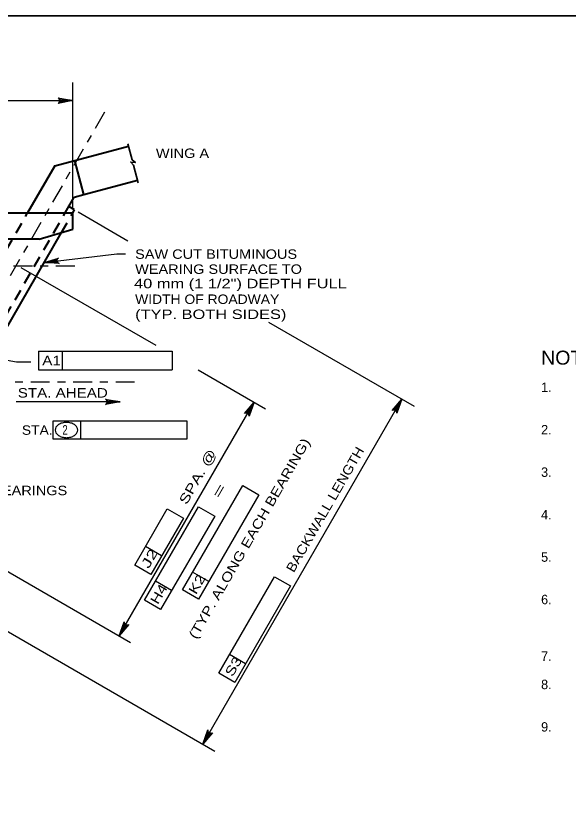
# Model space of a CAD drawing. Extents: x -11 to 79, y -154 to 0.
# Drawn here: x 16.53 to 23.56, y -120.79 to -110.75 of the extents above; entities that cross this region are included whole.
import ezdxf
from ezdxf.enums import TextEntityAlignment as Align

# ---------------------------------------------------------------- set-up
doc = ezdxf.new("R2010")
doc.units = 0
doc.header["$LTSCALE"] = 0.048
doc.linetypes.add('DOT_DASHED', pattern=[7.7, 5, -1.2, 0.3, -1.2])
doc.linetypes.add('MEDIUM_DASHED', pattern=[4.5, 3, -1.5])
for name, color, linetype, lineweight in [('1', 7, 'Continuous', 25), ('2', 7, 'Continuous', 35), ('3', 7, 'Continuous', 25), ('4', 7, 'Continuous', 25)]:
    doc.layers.add(name, color=color, linetype=linetype, lineweight=lineweight)

msp = doc.modelspace()

# ---------------------------------------------------------------- hatches: boundary and pattern name
at = {"layer": '4'}
for points in [[(21.36575, -115.71767), (21.40042, -115.73767), (21.44308, -115.62375)], [(19.48925, -115.75067), (19.522, -115.76958), (19.56233, -115.66192)], [(17.8855, -118.52842), (17.91825, -118.54733), (17.84517, -118.63608)]]:
    msp.add_hatch(color=256, dxfattribs=at).paths.add_polyline_path(points)

# ---------------------------------------------------------------- linework, layer by layer
at = {"layer": '1', "lineweight": 35}
msp.add_lwpolyline([(1.75, -131.25), (33.25, -131.25), (33.25, -110.75), (1.75, -110.75)], close=True, dxfattribs=at)
at = {"layer": '2', "lineweight": 40}
for p, q in [((17.02708, -112.66017), (17.96425, -112.409)), ((17.39675, -113.02383), (17.28108, -112.59208)), ((17.02708, -112.66017), (16.68192, -113.258)), ((17.39675, -113.02383), (18.07992, -112.84075)), ((17.27575, -113.05625), (17.39675, -113.02383)), ((17.15925, -113.258), (17.27575, -113.05625)), ((17.2795, -113.21992), (17.20583, -113.17733)), ((17.25742, -113.25808), (17.2795, -113.21992)), ((9.11433, -113.25808), (17.25742, -113.25808)), ((9.33183, -113.258), (17.15925, -113.258)), ((17.25742, -113.46475), (17.25742, -113.25808)), ((14.91208, -117.32042), (17.11392, -113.50675)), ((16.82825, -113.59025), (17.25742, -113.46475)), ((16.82825, -113.59025), (9.61733, -113.59025))]:
    msp.add_line(p, q, dxfattribs=at)
at = {"layer": '2', "linetype": 'MEDIUM_DASHED', "lineweight": 40}
for p, q in [((14.21717, -117.52708), (16.68192, -113.258)), ((17.01567, -113.50667), (17.15925, -113.258)), ((17.11392, -113.50675), (17.25742, -113.25808)), ((14.81383, -117.32042), (17.01567, -113.50667))]:
    msp.add_line(p, q, dxfattribs=at)
at = {"layer": '3', "lineweight": 35}
for p, q in [((18.011, -112.5835), (17.956, -112.3785)), ((18.08883, -112.87417), (18.02883, -112.65017))]:
    msp.add_line(p, q, dxfattribs=at)
msp.add_lwpolyline([(18.011, -112.5835), (18.053, -112.61483), (17.99325, -112.61125), (18.02883, -112.65017)], dxfattribs=at)
at = {"layer": '4'}
for p, q in [((17.25742, -112.23542), (17.25742, -111.59975)), ((9.11433, -111.82925), (17.25742, -111.82925)), ((17.25742, -113.19375), (17.25742, -112.23542)), ((17.32317, -113.24508), (17.95842, -113.61192)), ((16.89358, -113.88833), (17.81508, -113.77775)), ((17.81508, -113.77775), (17.9285, -113.77775)), ((16.59658, -113.94958), (18.31108, -114.9395)), ((19.747, -114.64458), (21.599, -115.71383)), ((16.81958, -115.01583), (18.52033, -115.01583)), ((16.81958, -115.01583), (16.81958, -115.252)), ((17.122, -115.01583), (17.122, -115.252)), ((18.52033, -115.01583), (18.52033, -115.252)), ((16.29683, -115.10933), (16.54258, -115.15067)), ((16.54258, -115.15067), (16.7215, -115.15067)), ((16.81958, -115.252), (18.52033, -115.252)), ((18.84983, -115.25058), (19.70958, -115.74692)), ((18.90975, -120.01167), (21.44308, -115.62375)), ((17.85825, -115.65892), (16.5365, -115.65892)), ((17.84517, -118.636), (19.56233, -115.66192)), ((17.84517, -118.63608), (19.56233, -115.66192)), ((17.35692, -116.136), (17.35692, -115.89983)), ((18.65017, -118.05083), (19.41967, -116.7235)), ((19.41967, -116.7235), (19.62425, -116.84158)), ((19.62425, -116.84158), (18.85475, -118.169)), ((14.87942, -116.92375), (17.9925, -118.72108)), ((18.16883, -118.1805), (18.85783, -116.99625)), ((18.85783, -116.99625), (19.06242, -117.11433)), ((19.06242, -117.11433), (18.37342, -118.29858)), ((18.38675, -117.61708), (18.18225, -117.499)), ((14.80025, -117.63908), (19.06558, -120.10167)), ((18.249, -117.85575), (18.04442, -117.73767)), ((18.98533, -117.94283), (18.78075, -117.82475)), ((18.512, -118.06042), (18.30783, -117.94158)), ((19.11258, -119.11192), (19.82192, -117.88342)), ((19.82192, -117.88342), (20.02642, -118.0015)), ((18.85475, -118.169), (18.65017, -118.05083)), ((18.37342, -118.29858), (18.16883, -118.1805)), ((19.455, -118.99133), (19.25042, -118.87325))]:
    msp.add_line(p, q, dxfattribs=at)
at = {"layer": '4', "linetype": 'DOT_DASHED'}
for p, q in [((17.66008, -111.97717), (13.89925, -118.49117)), ((17.28283, -113.93625), (3.36083, -113.93625)), ((18.04217, -115.40917), (6.3505, -115.40917))]:
    msp.add_line(p, q, dxfattribs=at)
at = {"layer": '4'}
for points in [[(17.25742, -111.82925), (17.071, -111.86417), (17.08533, -111.85425), (17.09275, -111.84175), (17.09492, -111.82925), (17.09275, -111.81675), (17.08533, -111.80425), (17.071, -111.79433), (17.25742, -111.82925), (17.08533, -111.80425), (17.09275, -111.81675), (17.25742, -111.82925), (17.09492, -111.82925), (17.09275, -111.84175), (17.25742, -111.82925), (17.08533, -111.85425)], [(16.89358, -113.88833), (17.0745, -113.83142), (17.06142, -113.843), (17.05558, -113.85633), (17.05492, -113.869), (17.05858, -113.88117), (17.06742, -113.89267), (17.08283, -113.90083), (16.89358, -113.88833), (17.06742, -113.89267), (17.05858, -113.88117), (16.89358, -113.88833), (17.05492, -113.869), (17.05558, -113.85633), (16.89358, -113.88833), (17.06142, -113.843)], [(17.85825, -115.65892), (17.67183, -115.69383), (17.68617, -115.68392), (17.69358, -115.67142), (17.69575, -115.65892), (17.69358, -115.64642), (17.68617, -115.63392), (17.67183, -115.624), (17.85825, -115.65892), (17.68617, -115.63392), (17.69358, -115.64642), (17.85825, -115.65892), (17.69575, -115.65892), (17.69358, -115.67142), (17.85825, -115.65892), (17.68617, -115.68392)], [(21.44308, -115.62375), (21.38017, -115.80267), (21.37875, -115.78525), (21.37158, -115.77258), (21.36183, -115.7645), (21.34992, -115.76008), (21.33542, -115.76025), (21.31958, -115.76775), (21.44308, -115.62375), (21.33542, -115.76025), (21.34992, -115.76008), (21.44308, -115.62375), (21.36183, -115.7645), (21.37158, -115.77258), (21.44308, -115.62375), (21.37875, -115.78525)], [(19.56233, -115.66192), (19.49942, -115.84083), (19.49792, -115.82342), (19.49083, -115.81075), (19.48108, -115.80267), (19.46917, -115.79825), (19.45467, -115.79842), (19.43883, -115.80592), (19.56233, -115.66192), (19.45467, -115.79842), (19.46917, -115.79825), (19.56233, -115.66192), (19.48108, -115.80267), (19.49083, -115.81075), (19.56233, -115.66192), (19.49792, -115.82342)], [(18.04442, -117.73767), (18.45892, -117.01975), (18.6635, -117.13792), (18.249, -117.85575)], [(20.02642, -118.0015), (19.31717, -119.23), (19.11258, -119.11192)], [(17.84517, -118.636), (17.90808, -118.45708), (17.90958, -118.4745), (17.91667, -118.48717), (17.92642, -118.49525), (17.93833, -118.49967), (17.95283, -118.4995), (17.96867, -118.492), (17.84517, -118.636), (17.95283, -118.4995), (17.93833, -118.49967), (17.84517, -118.636), (17.92642, -118.49525), (17.91667, -118.48717), (17.84517, -118.636), (17.90958, -118.4745)], [(18.90975, -120.01167), (18.97267, -119.83275), (18.97408, -119.85017), (18.98125, -119.86283), (18.991, -119.87092), (19.00292, -119.87533), (19.01742, -119.87517), (19.03325, -119.86767), (18.90975, -120.01167), (19.01742, -119.87517), (19.00292, -119.87533), (18.90975, -120.01167), (18.991, -119.87092), (18.98125, -119.86283), (18.90975, -120.01167), (18.97408, -119.85017)]]:
    msp.add_lwpolyline(points, dxfattribs=at)
for points in [[(21.36575, -115.71767), (21.40042, -115.73767), (21.44308, -115.62375)], [(19.48925, -115.75067), (19.522, -115.76958), (19.56233, -115.66192)], [(17.007, -116.136), (17.007, -115.89983), (18.70783, -115.89983), (18.70783, -116.136)], [(17.8855, -118.52842), (17.91825, -118.54733), (17.84517, -118.63608)]]:
    msp.add_lwpolyline(points, close=True, dxfattribs=at)
for centre, radius, start, end in [((17.13663, -116.04072), 0.10986, 124.10897, 148.55069), ((17.16062, -116.07614), 0.15263, 105.67084, 124.10897), ((17.17633, -116.13214), 0.2108, 90, 105.67084), ((17.17633, -116.13214), 0.2108, 74.32916, 90), ((17.19204, -116.07614), 0.15263, 55.89103, 74.32916), ((17.21602, -116.04072), 0.10986, 31.44931, 55.89103), ((17.10009, -116.01837), 0.06702, 148.55069, 180), ((17.10009, -116.01837), 0.06702, 180, 211.44931), ((17.13663, -115.99602), 0.10986, 211.44931, 235.89103), ((17.21602, -115.99602), 0.10986, 304.10897, 328.55069), ((17.25257, -116.01837), 0.06702, 0, 31.44931), ((17.25257, -116.01837), 0.06702, 328.55069, 0), ((17.16062, -115.9606), 0.15263, 235.89103, 254.32916), ((17.17633, -115.90461), 0.2108, 254.32916, 270), ((17.17633, -115.90461), 0.2108, 270, 285.67084), ((17.19204, -115.9606), 0.15263, 285.67084, 304.10897)]:
    msp.add_arc(centre, radius, start, end, dxfattribs=at)

# ---------------------------------------------------------------- texts
for s, height, width, p in [('WING A', 0.12, 1.15, (18.31383, -112.55833)), ('SAW CUT BITUMINOUS', 0.12, 1.15, (18.04967, -113.84092)), ('WEARING SURFACE TO', 0.12, 1.15, (18.04967, -114.03217)), ('40 mm (1 1/2") DEPTH FULL', 0.12, 1.3, (18.03592, -114.21492)), ('WIDTH OF ROADWAY', 0.12, 1.1, (18.04967, -114.41458)), ('(TYP. BOTH SIDES)', 0.12, 1.3, (18.04967, -114.60583)), ('NOTES:', 0.1772, 1.05, (23.21392, -115.18617)), ('STA. AHEAD', 0.12, 1.2, (16.55675, -115.60542)), ('STA.', 0.12, 1.1, (16.6085, -116.07892)), ('2', 0.12, 0.75, (17.12433, -116.07667)), ('C BEARINGS', 0.12, 1.15, (16.04792, -116.84692))]:
    msp.add_text(s, height=height, dxfattribs=dict(at, width=width)).set_placement(p)
for s, rotation, width, p in [('A1', 359.938, 1.2, (16.98644, -115.19396)), ('J2', 60, 1.5, (18.28451, -117.67992)), ('H4', 59.809, 1.25, (18.40308, -118.13401)), ('S3', 60, 1.3, (19.35243, -119.05467))]:
    msp.add_text(s, height=0.12, rotation=rotation, dxfattribs=dict(at, width=width)).set_placement(p, align=Align.CENTER)
for s, p in [('1.', (23.21392, -115.53375)), ('2.', (23.21392, -116.07375)), ('3.', (23.21392, -116.61375)), ('4.', (23.21392, -117.15375)), ('5.', (23.21392, -117.69375)), ('6.', (23.21392, -118.23375)), ('7.', (23.21392, -118.95375)), ('8.', (23.21392, -119.31375)), ('9.', (23.21392, -119.85375))]:
    msp.add_text(s, height=0.12, dxfattribs=at).set_placement(p)
for s, width, p in [('(TYP. ALONG EACH BEARING)', 1.25, (18.82775, -118.6865)), ('BACKWALL LENGTH', 1.15, (20.067, -117.84017)), ('SPA. @', 1.35, (18.704, -116.9765)), ('= ', 1.9, (19.12492, -116.89842)), ('K2', 1.3, (18.82517, -118.11925))]:
    msp.add_text(s, height=0.12, rotation=60, dxfattribs=dict(at, width=width)).set_placement(p)

doc.saveas('drawing.dxf')
